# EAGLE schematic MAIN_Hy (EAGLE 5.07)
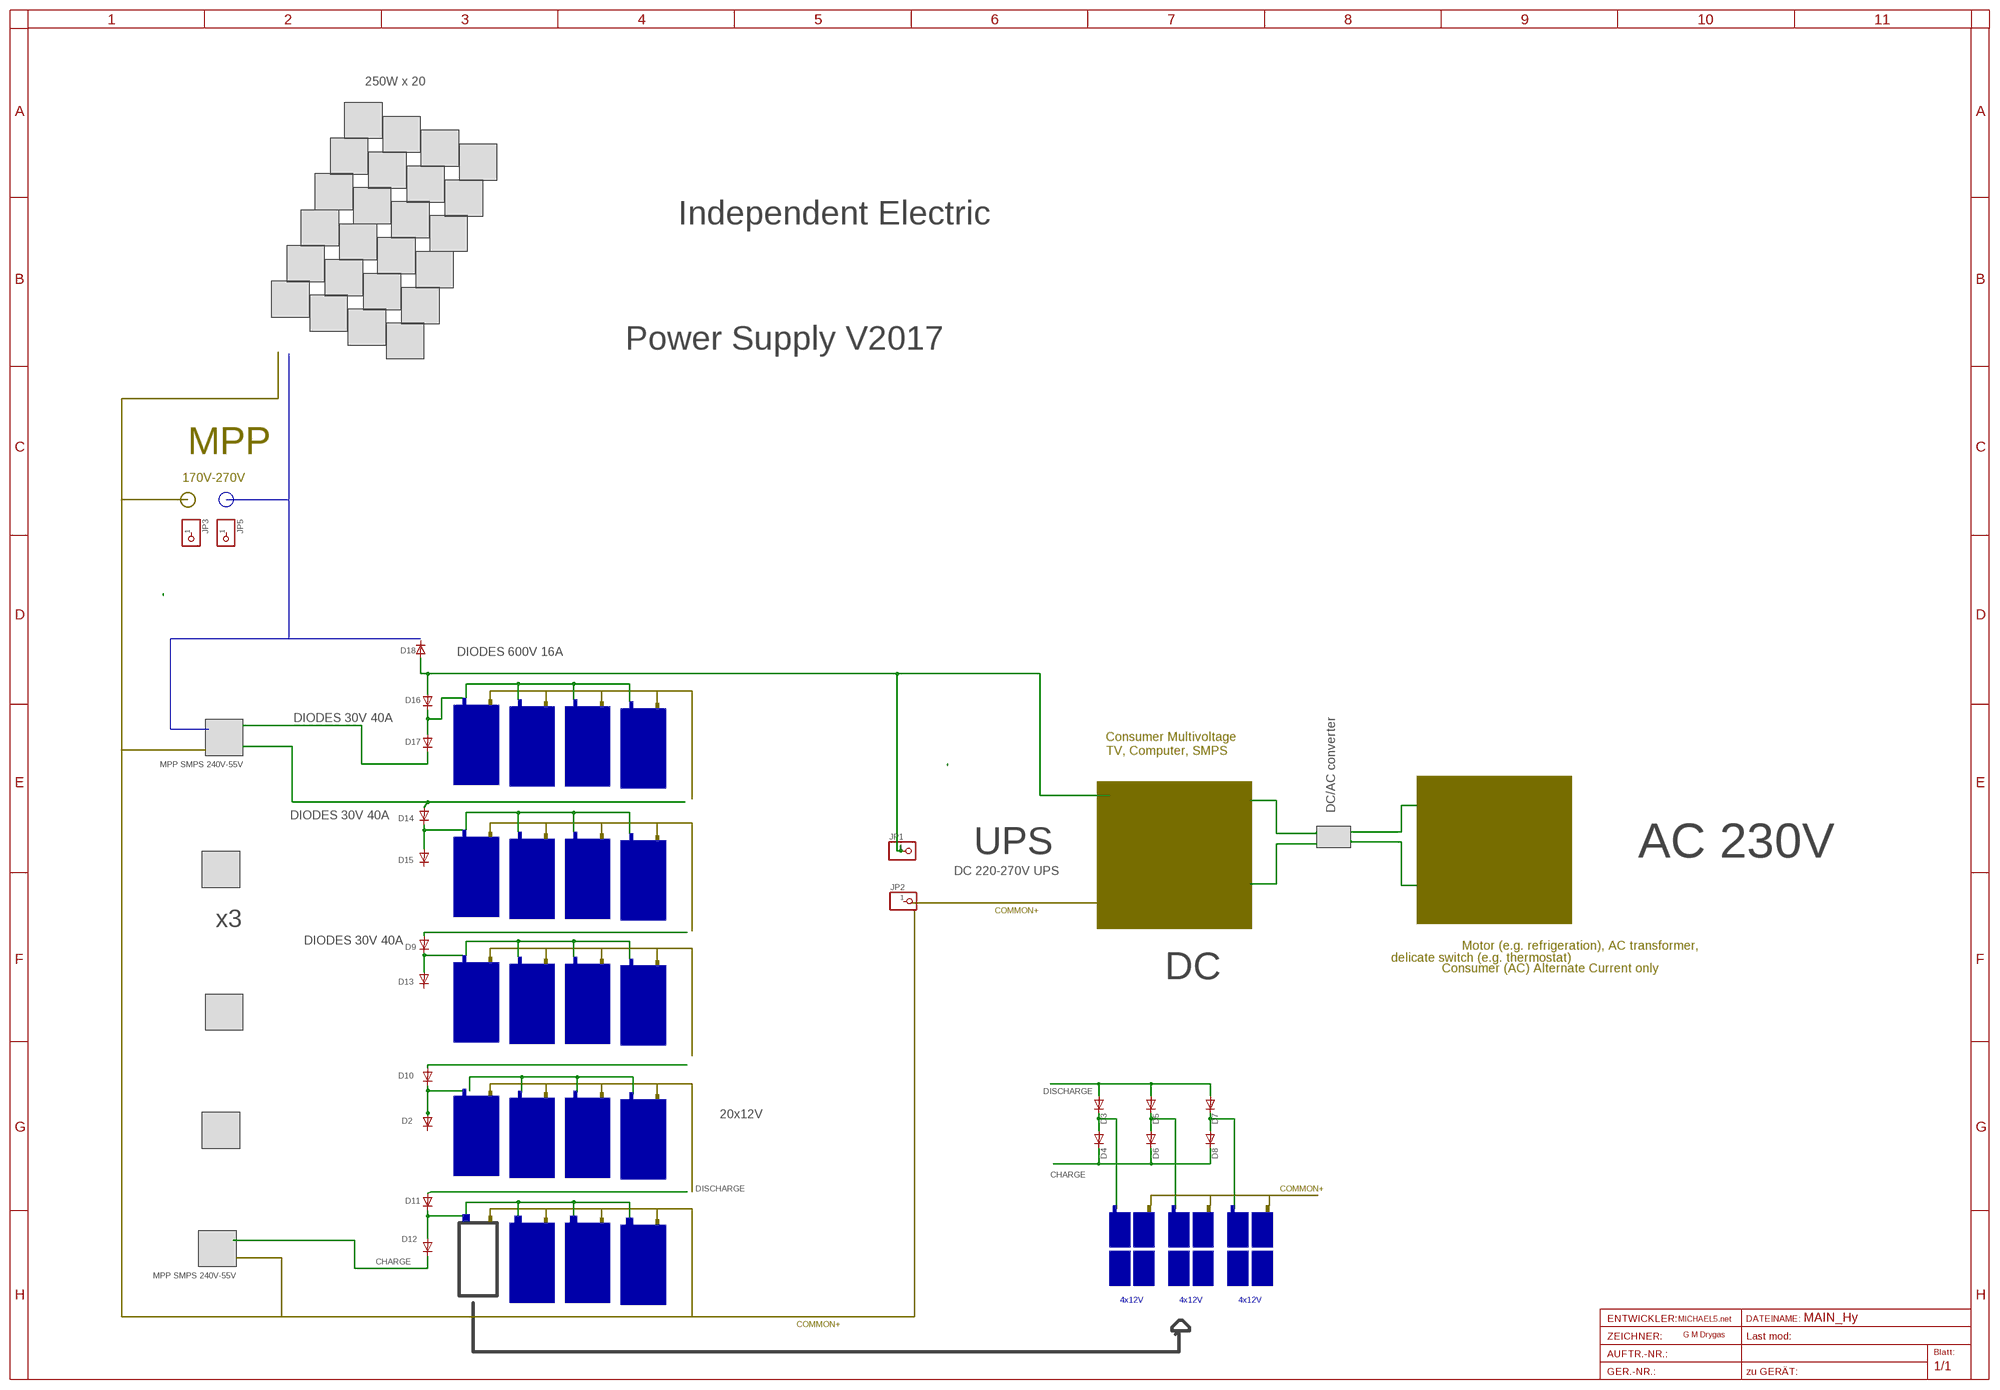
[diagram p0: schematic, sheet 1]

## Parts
D2  DIODE-SMC  [SMC]
D3  DIODE-SMC  [SMC]
D4  DIODE-SMC  [SMC]
D5  DIODE-SMC  [SMC]
D6  DIODE-SMC  [SMC]
D7  DIODE-SMC  [SMC]
D8  DIODE-SMC  [SMC]
D9  DIODE-SMC  [SMC]
D10  DIODE-SMC  [SMC]
D11  DIODE-SMC  [SMC]
D12  DIODE-SMC  [SMC]
D13  DIODE-SMC  [SMC]
D14  DIODE-SMC  [SMC]
D15  DIODE-SMC  [SMC]
D16  DIODE-SMC  [SMC]
D17  DIODE-SMC  [SMC]
D18  DIODE-SMC  [SMC]
JP1  PINHD-1X14.5MM  [1X4MM5]
JP2  PINHD-1X14.5MM  [1X4MM5]
JP3  PINHD-1X14.5MM  [1X4MM5]
JP5  PINHD-1X14.5MM  [1X4MM5]

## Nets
CHARGE: D4.C D6.C D8.C D12.C
DISCHARGE: D3.A D5.A D7.A D11.A
N$7: D9.A D14.A
N$12: D11.C D12.A
N$14: D2.A D10.C
N$15: D10.A
N$16: D14.C D15.A
N$17: D18.A JP1.1
N$19: D16.C D17.A
N$20: D9.C
N$21: D17.C
N$24: D3.C D4.A
N$27: D5.C D6.A
N$30: D7.C D8.A
Unconnected: D2.C D13.A D13.C D15.C D16.A D18.C JP2.1 JP3.1 JP5.1

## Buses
B$1
B$2

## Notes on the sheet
- 250W x 20
- Independent Electric
- Power Supply V2017
- MPP
- 170V-270V
- DIODES 600V 16A
- DIODES 30V 40A
- Consumer Multivoltage
- TV, Computer, SMPS
- MPP SMPS 240V-55V
- DIODES 30V 40A | DC/AC converter
- UPS | AC 230V
- DC 220-270V UPS
- COMMON+
- x3
- DIODES 30V 40A
- Motor (e.g. refrigeration), AC transformer,
- delicate switch (e.g. thermostat) | Consumer (AC) Alternate Current only
- DC
- 20x12V
- COMMON+
- MPP SMPS 240V-55V
- 4x12V | 4x12V | 4x12V
- MICHAEL5.net
- COMMON+
- G M Drygas

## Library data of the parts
D2-D18 = diode:DIODE-: DIODE
JP1-JP3 JP5 = pinhead:PINHD-1X1: PIN HEADER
